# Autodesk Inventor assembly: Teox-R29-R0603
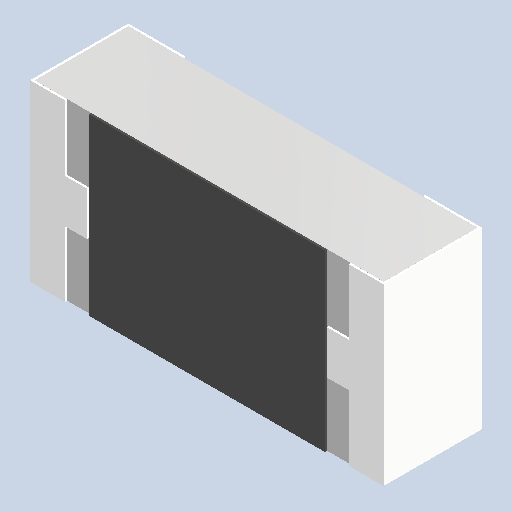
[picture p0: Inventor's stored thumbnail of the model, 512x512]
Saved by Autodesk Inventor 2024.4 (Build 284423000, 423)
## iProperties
Created: 2025-05
Part Number: Teox-R29-R0603
Document SubType Name: Assembly
Designer: AdminForWorker
Title: Teox-R29-R0603
Author: AdminForWorker
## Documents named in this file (2)
- c:\worker\convert-fusion-r02-cosv3\tmp\job-1\2\temp\files\be827049-a7f2-47ea-a815-8d9efd6bfce9\Teox-R29-R0603.iam
- c:\worker\convert-fusion-r02-cosv3\tmp\job-1\2\temp\files\be827049-a7f2-47ea-a815-8d9efd6bfce9\COMPOUND (2).ipt
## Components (1 placed, 1 different names)
1. COMPOUND (2):5
